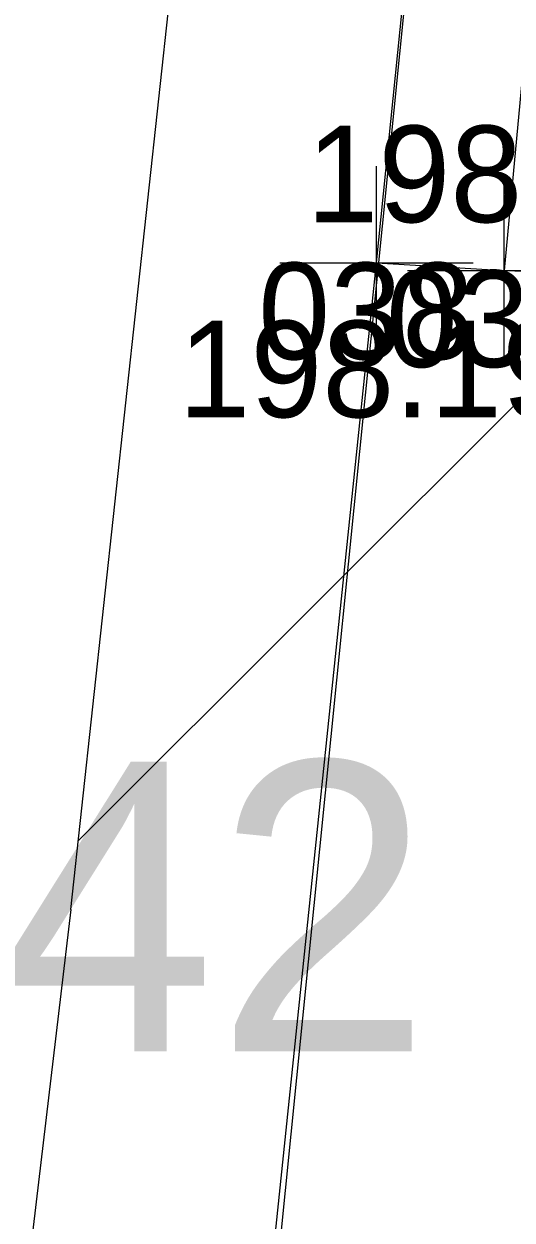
# Model space of a CAD drawing. Extents: x -706655 to -706193, y -1036183 to -1034979.
# Drawn here: x -706608.67 to -706606.15, y -1035107.9 to -1035101.7 of the extents above; entities that cross this region are included whole.
import ezdxf

# ---------------------------------------------------------------- set-up
doc = ezdxf.new("R2010")
doc.units = 0
for name, color, linetype in [('křížky', 7, 'Continuous'), ('Nová vrstva (0)', 7, 'Continuous'), ('Nová vrstva (1)', 7, 'Continuous'), ('Nová vrstva (4)', 7, 'Continuous'), ('Stávající terén', 7, 'Continuous'), ('výšky', 7, 'Continuous'), ('čísla bodu', 7, 'Continuous')]:
    doc.layers.add(name, color=color, linetype=linetype)

msp = doc.modelspace()

# ---------------------------------------------------------------- linework, layer by layer
at = {"layer": 'křížky'}
for p, q in [((-706606.85, -1035103.44), (-706606.85, -1035102.44)), ((-706606.19, -1035103.48), (-706606.19, -1035102.48)), ((-706607.35, -1035102.94), (-706606.35, -1035102.94)), ((-706606.85, -1035102.94), (-706606.85, -1035102.94)), ((-706606.69, -1035102.98), (-706605.69, -1035102.98)), ((-706606.19, -1035102.98), (-706606.19, -1035102.98))]:
    msp.add_line(p, q, dxfattribs=at)
at = {"layer": 'Nová vrstva (1)'}
msp.add_line((-706606.2341, -1035096.8972), (-706608.0683, -1035115.1753), dxfattribs=at)
at = {"layer": 'Nová vrstva (4)'}
for p, q in [((-706608.43, -1035106.29), (-706595.5132, -1034986.9872)), ((-706608.3912, -1035105.9312), (-706603.8388, -1035101.3789)), ((-706608.43, -1035106.29), (-706622.5524, -1035225.4561))]:
    msp.add_line(p, q, dxfattribs=at)
at = {"layer": 'Stávající terén'}
msp.add_line((-706606.85, -1035102.94), (-706606.19, -1035102.98), dxfattribs=at)
for points in [[(-706612.08, -1035147.45), (-706609.84, -1035129.45), (-706609.56, -1035126.63), (-706608.3, -1035116.88), (-706606.85, -1035102.94), (-706605.26, -1035087.23), (-706604.17, -1035076.55)], [(-706603.54, -1035076.59), (-706604.73, -1035087.33), (-706606.19, -1035102.98), (-706603.68, -1035103.06)]]:
    msp.add_lwpolyline(points, dxfattribs=at)
at = {"layer": 'čísla bodu'}
for p, q in [((-706606.85, -1035103.44), (-706606.85, -1035102.44)), ((-706606.19, -1035103.48), (-706606.19, -1035102.48)), ((-706607.35, -1035102.94), (-706606.35, -1035102.94)), ((-706606.85, -1035102.94), (-706606.85, -1035102.94)), ((-706606.69, -1035102.98), (-706605.69, -1035102.98)), ((-706606.19, -1035102.98), (-706606.19, -1035102.98))]:
    msp.add_line(p, q, dxfattribs=at)

# ---------------------------------------------------------------- texts
at = {"layer": 'Nová vrstva (0)'}
msp.add_text('0,242', height=1.5, dxfattribs=at).set_placement((-706611.5869, -1035107.0236))
at = {"layer": 'výšky'}
for s, p in [('198.15', (-706607.212, -1035102.73)), ('198.19', (-706607.874, -1035103.74))]:
    msp.add_text(s, height=0.5, dxfattribs=at).set_placement(p)
at = {"layer": 'čísla bodu'}
for s, p in [('038', (-706607.462, -1035103.44)), ('037', (-706606.802, -1035103.48))]:
    msp.add_text(s, height=0.5, dxfattribs=at).set_placement(p)

doc.saveas('drawing.dxf')
